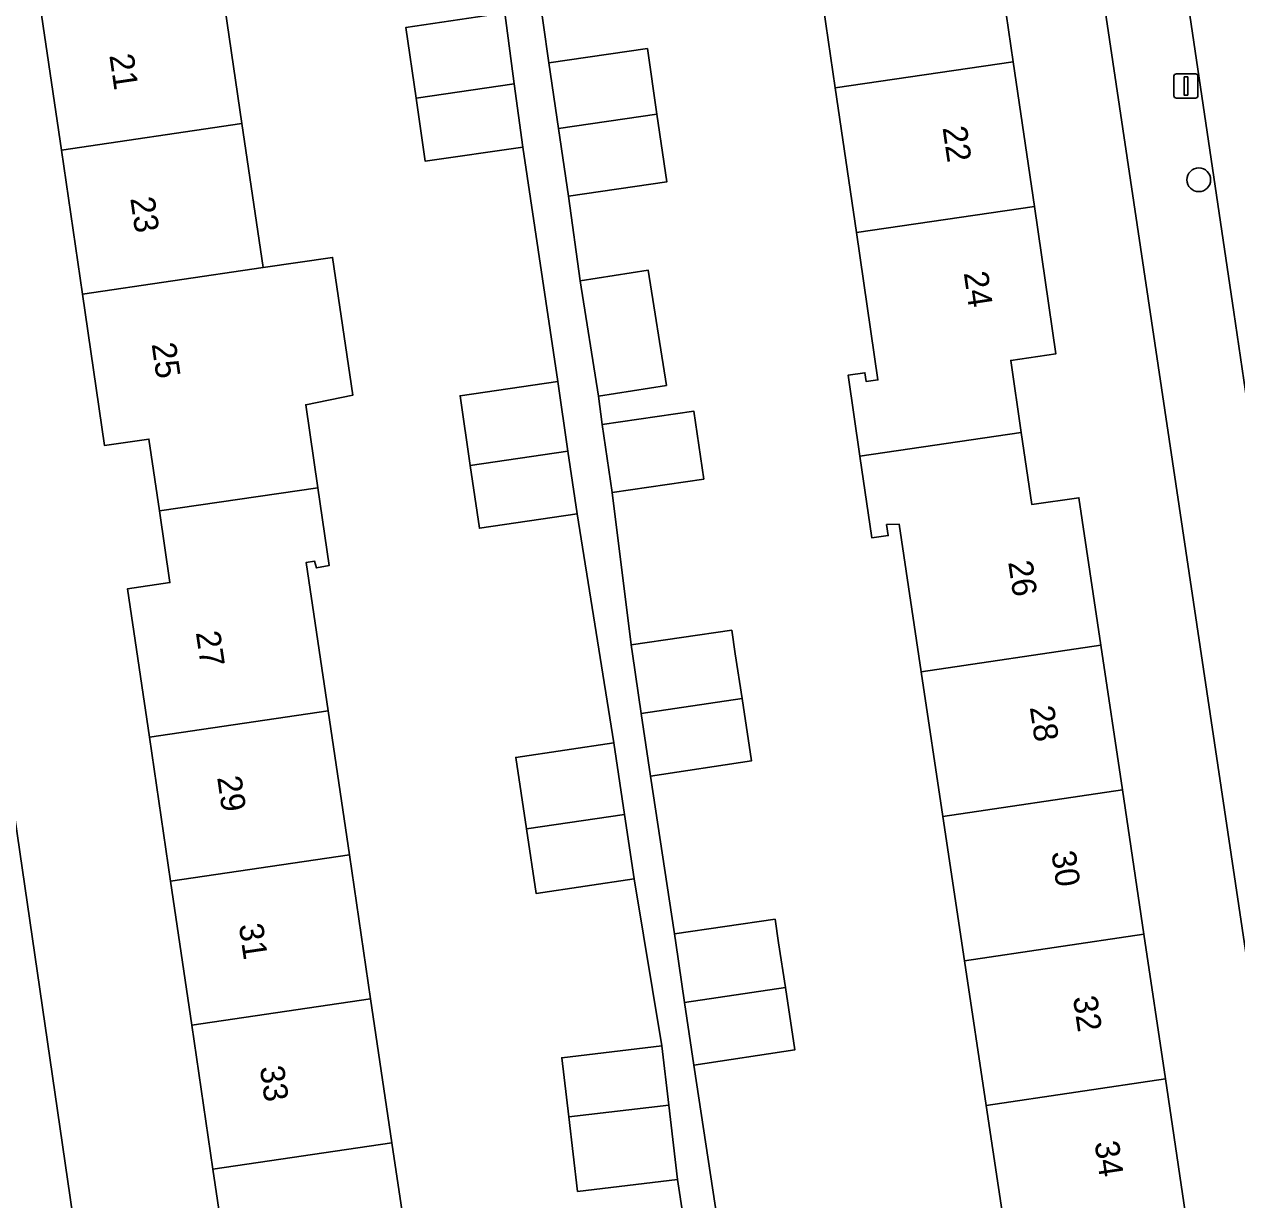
# Model space of a CAD drawing. Extents: x 159053 to 160042, y 380449 to 381423.
# Drawn here: x 159396.8 to 159446.78, y 381001.32 to 381049.76 of the extents above; entities that cross this region are included whole.
import ezdxf

# ---------------------------------------------------------------- set-up
doc = ezdxf.new("R2010")
doc.units = 0
for name, color, linetype in [('IMGEO_Boom', 7, 'Continuous'), ('IMGEO_Erf', 7, 'Continuous'), ('IMGEO_Lichtmast', 7, 'Continuous'), ('IMGEO_Pand', 7, 'Continuous'), ('IMGEO_Pand_nummerreeks', 7, 'Continuous'), ('IMGEO_Rijbaan_lokaal_open', 7, 'Continuous'), ('IMGEO_Voetpad_open', 7, 'Continuous')]:
    doc.layers.add(name, color=color, linetype=linetype)

msp = doc.modelspace()

# ---------------------------------------------------------------- linework, layer by layer
at = {"layer": 'IMGEO_Boom'}
msp.add_circle((159445.214, 381043.35), 0.489, dxfattribs=at)
at = {"layer": 'IMGEO_Erf'}
for points in [[(159434.441, 381090.362), (159431.45, 381090.013), (159432.338, 381083.946), (159433.209, 381077.989), (159434.081, 381072.032), (159434.952, 381066.076), (159435.824, 381060.119), (159436.695, 381054.163), (159437.567, 381048.206), (159438.439, 381042.249), (159439.327, 381036.178), (159437.465, 381035.905), (159437.899, 381032.935), (159438.333, 381029.965), (159440.276, 381030.249), (159441.181, 381024.168), (159442.067, 381018.214), (159442.953, 381012.26), (159443.84, 381006.305), (159444.726, 381000.351), (159444.778, 381000), (159445.63, 380994.272), (159449.622, 380994.989)], [(159448.874, 381000), (159435.479, 381089.722)], [(159399.195, 381038.639), (159398.327, 381044.576), (159397.458, 381050.512), (159396.589, 381056.449), (159395.72, 381062.386), (159394.852, 381068.323), (159393.983, 381074.259), (159393.114, 381080.196), (159392.201, 381086.438), (159386.866, 381085.411)], [(159386.52, 381084.815), (159398.888, 381000), (159401.289, 380983.538), (159407.214, 380984.584), (159406.316, 380990.699), (159405.443, 380996.635), (159404.949, 381000), (159404.571, 381002.571), (159403.699, 381008.508), (159402.826, 381014.444), (159401.954, 381020.38), (159401.055, 381026.497), (159402.8, 381026.752), (159402.368, 381029.705), (159401.936, 381032.662), (159400.109, 381032.395), (159399.195, 381038.639)], [(159437.232, 381000), (159436.451, 381005.205), (159435.559, 381011.159), (159434.666, 381017.113), (159433.773, 381023.066), (159432.859, 381029.164), (159432.346, 381029.138), (159432.411, 381028.69), (159431.741, 381028.592), (159431.248, 381031.961), (159430.76, 381035.295), (159431.45, 381035.396), (159431.501, 381035.041), (159431.989, 381035.104), (159431.101, 381041.176), (159430.229, 381047.133), (159429.357, 381053.09)], [(159404.902, 381051.602), (159405.771, 381045.666), (159406.639, 381039.729), (159409.507, 381040.149), (159410.339, 381034.469), (159408.4, 381034.081), (159408.9, 381030.661), (159409.369, 381027.456), (159408.849, 381027.352), (159408.761, 381027.632), (159408.415, 381027.574), (159409.319, 381021.463), (159410.197, 381015.527), (159411.075, 381009.592), (159411.953, 381003.656), (159412.494, 381000)], [(159417.949, 381051.477), (159418.426, 381048.166), (159422.483, 381048.759), (159422.878, 381046.058), (159423.287, 381043.268), (159419.23, 381042.675), (159419.71, 381039.179), (159422.515, 381039.625), (159423.271, 381034.874), (159420.466, 381034.428), (159420.618, 381033.265), (159424.396, 381033.818), (159424.807, 381031.012), (159421.028, 381030.459), (159421.816, 381024.179), (159425.961, 381024.786), (159426.108, 381023.814), (159426.387, 381021.967), (159426.775, 381019.401), (159422.61, 381018.776), (159423.602, 381012.272), (159427.747, 381012.879), (159427.894, 381011.907), (159428.173, 381010.059), (159428.561, 381007.494), (159424.396, 381006.869), (159425.387, 381000.365)], [(159424.611, 380996.408), (159423.727, 381002.15), (159419.609, 381001.662), (159419.246, 381004.728), (159418.956, 381007.171), (159423.074, 381007.659), (159421.94, 381014.546), (159417.895, 381013.939), (159417.496, 381016.599), (159417.054, 381019.542), (159421.099, 381020.149), (159419.588, 381029.579), (159415.562, 381028.99), (159415.183, 381031.581), (159414.764, 381034.447), (159418.79, 381035.036), (159417.344, 381044.7), (159413.327, 381044.112), (159412.946, 381046.717), (159412.52, 381049.624), (159416.611, 381050.223)]]:
    msp.add_lwpolyline(points, dxfattribs=at)
at = {"layer": 'IMGEO_Lichtmast'}
for p, q in [((159444.191, 381046.816), (159444.191, 381047.616)), ((159444.191, 381047.616), (159444.191, 381046.816)), ((159444.291, 381047.716), (159445.081, 381047.716)), ((159445.081, 381047.716), (159444.291, 381047.716)), ((159445.181, 381047.616), (159445.181, 381046.816)), ((159445.181, 381046.816), (159445.181, 381047.616)), ((159445.081, 381046.716), (159444.291, 381046.716)), ((159444.291, 381046.716), (159445.081, 381046.716))]:
    msp.add_line(p, q, dxfattribs=at)
msp.add_lwpolyline([(159444.611, 381047.591), (159444.761, 381047.591), (159444.761, 381046.841), (159444.611, 381046.841), (159444.611, 381047.591)], dxfattribs=at)
for centre, start, end in [((159444.291, 381047.616), 90, 180), ((159444.291, 381047.616), 90, 180), ((159445.081, 381047.616), 0, 90), ((159445.081, 381047.616), 360, 90), ((159444.291, 381046.816), 180, 270), ((159444.291, 381046.816), 180, 270), ((159445.081, 381046.816), 270, 0), ((159445.081, 381046.816), 270, 0)]:
    msp.add_arc(centre, 0.1, start, end, dxfattribs=at)
at = {"layer": 'IMGEO_Pand'}
for points in [[(159430.229, 381047.133), (159437.567, 381048.206), (159436.695, 381054.163), (159429.357, 381053.09)], [(159398.327, 381044.576), (159405.771, 381045.666), (159404.902, 381051.602), (159397.458, 381050.512)], [(159416.611, 381050.223), (159412.52, 381049.624), (159412.946, 381046.717), (159416.998, 381047.31)], [(159418.821, 381045.465), (159422.878, 381046.058), (159422.483, 381048.759), (159418.426, 381048.166)], [(159430.229, 381047.133), (159431.101, 381041.176), (159438.439, 381042.249), (159437.567, 381048.206)], [(159416.998, 381047.31), (159412.946, 381046.717), (159413.327, 381044.112), (159417.344, 381044.7)], [(159406.639, 381039.729), (159405.771, 381045.666), (159398.327, 381044.576), (159399.195, 381038.639)], [(159418.821, 381045.465), (159419.23, 381042.675), (159423.287, 381043.268), (159422.878, 381046.058)], [(159437.899, 381032.935), (159437.465, 381035.905), (159439.327, 381036.178), (159438.439, 381042.249), (159431.101, 381041.176), (159431.989, 381035.104), (159431.501, 381035.041), (159431.45, 381035.396), (159430.76, 381035.295), (159431.248, 381031.961)], [(159408.4, 381034.081), (159410.339, 381034.469), (159409.507, 381040.149), (159406.639, 381039.729), (159399.195, 381038.639), (159400.109, 381032.395), (159401.936, 381032.662), (159402.368, 381029.705), (159408.9, 381030.661)], [(159422.515, 381039.625), (159419.71, 381039.179), (159420.466, 381034.428), (159423.271, 381034.874)], [(159418.79, 381035.036), (159414.764, 381034.447), (159415.183, 381031.581), (159419.209, 381032.17)], [(159420.618, 381033.265), (159421.028, 381030.459), (159424.807, 381031.012), (159424.396, 381033.818)], [(159433.773, 381023.066), (159441.181, 381024.168), (159440.276, 381030.249), (159438.333, 381029.965), (159437.899, 381032.935), (159431.248, 381031.961), (159431.741, 381028.592), (159432.411, 381028.69), (159432.346, 381029.138), (159432.859, 381029.164)], [(159419.209, 381032.17), (159415.183, 381031.581), (159415.562, 381028.99), (159419.588, 381029.579)], [(159402.368, 381029.705), (159402.8, 381026.752), (159401.055, 381026.497), (159401.954, 381020.38), (159409.319, 381021.463), (159408.415, 381027.574), (159408.761, 381027.632), (159408.849, 381027.352), (159409.369, 381027.456), (159408.9, 381030.661)], [(159422.232, 381021.349), (159426.387, 381021.967), (159426.108, 381023.814), (159425.961, 381024.786), (159421.816, 381024.179), (159421.87, 381023.814)], [(159433.773, 381023.066), (159434.666, 381017.113), (159442.067, 381018.214), (159441.181, 381024.168)], [(159422.232, 381021.349), (159422.61, 381018.776), (159426.775, 381019.401), (159426.387, 381021.967)], [(159409.319, 381021.463), (159401.954, 381020.38), (159402.826, 381014.444), (159410.197, 381015.527)], [(159417.496, 381016.599), (159421.543, 381017.194), (159421.099, 381020.149), (159417.054, 381019.542)], [(159442.067, 381018.214), (159434.666, 381017.113), (159435.559, 381011.159), (159442.953, 381012.26)], [(159417.496, 381016.599), (159417.895, 381013.939), (159421.94, 381014.546), (159421.543, 381017.194)], [(159410.197, 381015.527), (159402.826, 381014.444), (159403.699, 381008.508), (159411.075, 381009.592)], [(159428.173, 381010.059), (159427.894, 381011.907), (159427.747, 381012.879), (159423.602, 381012.272), (159423.656, 381011.907), (159424.018, 381009.441)], [(159443.84, 381006.305), (159442.953, 381012.26), (159435.559, 381011.159), (159436.451, 381005.205)], [(159428.173, 381010.059), (159424.018, 381009.441), (159424.396, 381006.869), (159428.561, 381007.494)], [(159411.953, 381003.656), (159411.075, 381009.592), (159403.699, 381008.508), (159404.571, 381002.571)], [(159419.246, 381004.728), (159423.363, 381005.216), (159423.074, 381007.659), (159418.956, 381007.171)], [(159437.344, 380999.252), (159442.366, 381000), (159444.726, 381000.351), (159443.84, 381006.305), (159436.451, 381005.205), (159437.232, 381000)], [(159419.246, 381004.728), (159419.609, 381001.662), (159423.727, 381002.15), (159423.363, 381005.216)], [(159411.953, 381003.656), (159404.571, 381002.571), (159404.949, 381000), (159405.443, 380996.635), (159412.831, 380997.721), (159412.494, 381000)]]:
    msp.add_lwpolyline(points, close=True, dxfattribs=at)
at = {"layer": 'IMGEO_Rijbaan_lokaal_open'}
msp.add_lwpolyline([(159458.014, 381008.022), (159454.981, 381029.422), (159453.929, 381036.365), (159450.806, 381057.803), (159443.858, 381056.823), (159446.657, 381037.89), (159447.686, 381030.883), (159451.207, 381006.916)], close=True, dxfattribs=at)
at = {"layer": 'IMGEO_Voetpad_open'}
for points in [[(159434.725, 381116.398), (159431.519, 381116.656), (159433.919, 381100.289), (159434.916, 381093.497), (159435.479, 381089.722), (159448.874, 381000), (159449.622, 380994.989)], [(159447.686, 381030.883), (159446.657, 381037.89), (159443.858, 381056.823), (159443.344, 381060.378), (159437.701, 381098.967), (159437.198, 381102.422), (159435.439, 381114.494)], [(159398.888, 381000), (159386.52, 381084.815)], [(159425.387, 381000.365), (159424.396, 381006.869), (159424.018, 381009.441), (159423.656, 381011.907), (159423.602, 381012.272), (159422.61, 381018.776), (159422.232, 381021.349), (159421.87, 381023.814), (159421.816, 381024.179), (159421.028, 381030.459), (159420.618, 381033.265), (159420.466, 381034.428), (159419.71, 381039.179), (159419.23, 381042.675), (159418.821, 381045.465), (159418.426, 381048.166), (159417.949, 381051.477)], [(159416.611, 381050.223), (159416.998, 381047.31), (159417.344, 381044.7), (159418.79, 381035.036), (159419.209, 381032.17), (159419.588, 381029.579), (159421.099, 381020.149), (159421.543, 381017.194), (159421.94, 381014.546), (159423.074, 381007.659), (159423.363, 381005.216), (159423.727, 381002.15), (159424.611, 380996.408)]]:
    msp.add_lwpolyline(points, dxfattribs=at)

# ---------------------------------------------------------------- texts
at = {"layer": 'IMGEO_Pand_nummerreeks'}
for s, rotation, p in [('21', 278.3249, (159400.302, 381048.478)), ('22', 278.3243, (159434.649, 381045.497)), ('23', 278.3249, (159401.164, 381042.585)), ('24', 278.3243, (159435.524, 381039.512)), ('25', 278.3249, (159402.044, 381036.58)), ('26', 278.4653, (159437.356, 381027.594)), ('27', 278.3601, (159403.867, 381024.694)), ('28', 278.4653, (159438.246, 381021.612)), ('29', 278.3601, (159404.745, 381018.722)), ('30', 278.4653, (159439.135, 381015.632)), ('31', 278.3601, (159405.638, 381012.639)), ('32', 278.4653, (159440.024, 381009.658)), ('33', 278.3601, (159406.5, 381006.777)), ('34', 278.4653, (159440.915, 381003.676))]:
    msp.add_text(s, height=1, rotation=rotation, dxfattribs=at).set_placement(p)

doc.saveas('drawing.dxf')
